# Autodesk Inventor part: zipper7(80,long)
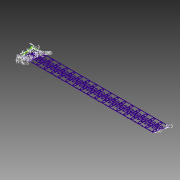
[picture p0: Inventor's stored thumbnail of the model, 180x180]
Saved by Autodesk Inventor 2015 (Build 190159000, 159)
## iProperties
Created: 2015-02
Part Number: zipper7(80,long)
Material: Generic
Document SubType Name: Modeling
Designer: sungeun
Density: 1 g/cm^3
Appearance: Default
Author: sungeun
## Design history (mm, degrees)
sketch "Sketch1"
  geometry: L1 (0, 2)-(8.682, 51.24); L2 (8.682, 51.24)-(14.682, 51.24); L3 (14.682, 51.24)-(23.365, 2); L4 (23.365, 2)-(29.365, 2); L5 (29.365, 0)-(0, 0); L6 (8.682, 38.62)-(14.682, 38.62); L7 (14.682, 38.62)-(14.682, 14.62); L8 (14.682, 14.62)-(8.682, 14.62); L9 (8.682, 14.62)-(8.682, 38.62); L10 (23.365, 38.62)-(29.365, 38.62); L11 (29.365, 38.62)-(29.365, 14.62); L12 (29.365, 14.62)-(23.365, 14.62); L13 (23.365, 14.62)-(23.365, 38.62); L14 (11.682, 53.24)-(41.047, 53.24); L15 (0, 2)-(-3, 2); L16 (-3, 53.24)-(11.682, 53.24); L17 (-3, 2)-(-6, 2); L18 (-6, 2)-(-14.682, 51.24); L19 (-14.682, 51.24)-(-17.682, 51.24); L20 (0, 0)-(-6, 0); L21 (-3, 53.24)-(-17.682, 53.24); L22 (-17.682, 53.24)-(-17.682, 51.24); L23 (41.047, 53.24)-(70.412, 53.24); L24 (38.047, 51.24)-(44.047, 51.24); L25 (44.047, 51.24)-(52.73, 2); L26 (29.365, 2)-(38.047, 51.24); L27 (38.047, 38.62)-(44.047, 38.62); L28 (38.047, 14.62)-(38.047, 38.62); L29 (44.047, 38.62)-(44.047, 14.62); L30 (44.047, 14.62)-(38.047, 14.62); L31 (58.73, 0)-(29.365, 0); L32 (52.73, 2)-(58.73, 2); L33 (58.73, 14.62)-(52.73, 14.62); L34 (58.73, 38.62)-(58.73, 14.62); L35 (52.73, 14.62)-(52.73, 38.62); L36 (52.73, 38.62)-(58.73, 38.62); L37 (70.412, 53.24)-(99.777, 53.24); L38 (67.412, 51.24)-(73.412, 51.24); L39 (73.412, 51.24)-(82.094, 2); L40 (58.73, 2)-(67.412, 51.24); L41 (67.412, 38.62)-(73.412, 38.62); L42 (67.412, 14.62)-(67.412, 38.62); L43 (73.412, 38.62)-(73.412, 14.62); L44 (73.412, 14.62)-(67.412, 14.62); L45 (88.094, 0)-(58.73, 0); L46 (82.094, 2)-(88.094, 2); L47 (88.094, 14.62)-(82.094, 14.62); L48 (88.094, 38.62)-(88.094, 14.62); L49 (82.094, 14.62)-(82.094, 38.62); L50 (82.094, 38.62)-(88.094, 38.62); L51 (99.777, 53.24)-(129.142, 53.24); L52 (96.777, 51.24)-(102.777, 51.24); L53 (102.777, 51.24)-(111.459, 2); L54 (88.094, 2)-(96.777, 51.24); L55 (96.777, 38.62)-(102.777, 38.62); L56 (96.777, 14.62)-(96.777, 38.62); L57 (102.777, 38.62)-(102.777, 14.62); L58 (102.777, 14.62)-(96.777, 14.62); L59 (117.459, 0)-(88.094, 0); L60 (111.459, 2)-(117.459, 2); L61 (117.459, 14.62)-(111.459, 14.62); L62 (117.459, 38.62)-(117.459, 14.62); L63 (111.459, 14.62)-(111.459, 38.62); L64 (111.459, 38.62)-(117.459, 38.62)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; 162 further points
  constraints: 528 end point, 9 midpoint, 7 horizontal, 7 vertical alignment, 6 parallel, 3 horizontal alignment, 3 perpendicular, 2 equal length, 2 vertical, 1 collinear, 1 point on line, 679 other
  dimensions: "d0" = 2 distance of L5.end L1.start; "d1" = 6 distance of L1.end L2.end; "d2" = 80 deg angle of L5 L1; "d4" = 2 distance between parallel lines of L5 L4 (= d0); "d34" = 6 distance of L3.end L4.end (= d1); "d35" = 23.36482 distance of L1.start L3.end (derived); "d36" = 50 distance of L1.start L1.end; "d44" = 6 distance of L7.end L8.end (= d1); "d45" = 24 distance of L8.end L6.start (= 4 x d1); "d46" = 6 distance of L11.end L12.end (= d1); "d47" = 24 distance of L12.end L10.start (= d45); "d55" = 2 distance between parallel lines of L2 L14 (= d4); "d56" = 29.36482 distance of L14.start L14.end (= d35 + d46); "d64" = 3 distance of L1.start L15.end (= 0.5 x d1); "d65" = 3 distance of L15.end L17.end (= 0.5 x d1); "d67" = 3 distance of L18.end L19.end (= 0.5 x d1); "d102" = 29.36482 distance of L14.start L23.start (derived); "d107" = 50 distance of L256.end L262.end; "d108" = 3 distance of L262.end L263.end (derived)
other parameters: "d6" = 56.39702 (derived)
